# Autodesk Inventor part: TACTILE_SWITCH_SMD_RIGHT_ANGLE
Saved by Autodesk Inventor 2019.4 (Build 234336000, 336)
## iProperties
Created: 2021-02
Part Number: TACTILE_SWITCH_SMD_RIGHT_ANGLE
Material: Generic
Document SubType Name: Modeling
Designer: Administrator
Density: 1 g/cm^3
Appearance: Default
Title: TACTILE_SWITCH_SMD_RIGHT_ANGLE
Author: Administrator
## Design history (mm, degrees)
feature "Body1"
body "Solid1"
